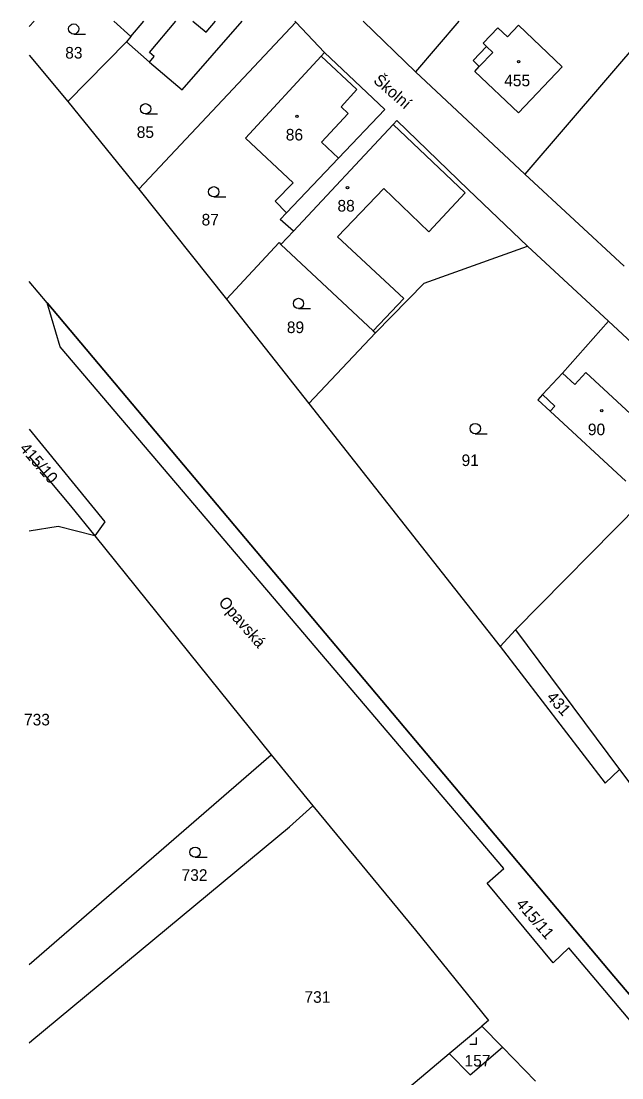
# Model space of a CAD drawing. Extents: x -504601 to -503665, y -1079870 to -1078626.
# Drawn here: x -504600.9 to -504513, y -1078780.8 to -1078626.2 of the extents above; entities that cross this region are included whole.
import ezdxf

# ---------------------------------------------------------------- set-up
doc = ezdxf.new("R2010")
doc.units = 0
for name, color, linetype in [('Hranice parcel', 7, 'Continuous'), ('Parcelní čísla', 7, 'Continuous'), ('Pop  PČ popisy', 7, 'Continuous'), ('Vnitřní kresba', 7, 'Continuous'), ('Vrstva 54', 7, 'Continuous'), ('Značky budov', 7, 'Continuous'), ('Značky kultur', 7, 'Continuous')]:
    doc.layers.add(name, color=color, linetype=linetype)

msp = doc.modelspace()

# ---------------------------------------------------------------- linework, layer by layer
at = {"layer": 'Hranice parcel'}
for p, q in [((-504599.72, -1078626.96), (-504598.99, -1078626.15)), ((-504587.33, -1078626.15), (-504584.87, -1078628.4)), ((-504583.69, -1078650.73), (-504560.74, -1078626.29)), ((-504560.74, -1078626.29), (-504560.89, -1078626.15)), ((-504556.52, -1078630.76), (-504560.74, -1078626.29)), ((-504550.86, -1078626.15), (-504543.22, -1078633.58)), ((-504536.89, -1078626.15), (-504543.22, -1078633.58)), ((-504508.05, -1078626.15), (-504527.23, -1078648.54)), ((-504594.06, -1078637.92), (-504585.52, -1078629.17)), ((-504584.87, -1078628.4), (-504585.52, -1078629.17)), ((-504599.72, -1078631.15), (-504594.06, -1078637.92)), ((-504543.22, -1078633.58), (-504527.23, -1078648.54)), ((-504594.06, -1078637.92), (-504583.69, -1078650.73)), ((-504527.23, -1078648.54), (-504512.71, -1078662.02)), ((-504583.69, -1078650.73), (-504570.88, -1078666.85)), ((-504563.74, -1078652.52), (-504562.08, -1078654.23)), ((-504561.09, -1078656.9), (-504562.9, -1078658.83)), ((-504515.01, -1078670.07), (-504526.83, -1078659.1)), ((-504595.19, -1078673.8), (-504597.09, -1078667.4)), ((-504570.88, -1078666.85), (-504558.84, -1078682.13)), ((-504515.01, -1078670.07), (-504521.74, -1078677.69)), ((-504497.46, -1078686.36), (-504515.01, -1078670.07)), ((-504558.84, -1078682.13), (-504549.08, -1078671.78)), ((-504558.84, -1078682.13), (-504530.83, -1078717.69)), ((-504528.6, -1078715.23), (-504510.4, -1078696.81)), ((-504590.14, -1078701.47), (-504564.35, -1078733.55)), ((-504530.83, -1078717.69), (-504528.6, -1078715.23)), ((-504528.6, -1078715.23), (-504513.37, -1078735.66)), ((-504564.35, -1078733.55), (-504558.23, -1078741)), ((-504513.37, -1078735.66), (-504512.16, -1078737.29)), ((-504538.29, -1078777.24), (-504533.54, -1078773.23)), ((-504533.54, -1078773.23), (-504530.49, -1078776.34)), ((-504525.66, -1078781.28), (-504530.49, -1078776.34)), ((-504599.72, -1078829.02), (-504538.29, -1078777.24))]:
    msp.add_line(p, q, dxfattribs=at)
for points in [[(-504585.52, -1078629.17), (-504582.12, -1078632.17), (-504577.37, -1078636.19), (-504568.57, -1078626.15)], [(-504584.87, -1078628.4), (-504582.98, -1078626.15)], [(-504533.89, -1078632.8), (-504534.81, -1078631.93), (-504532.83, -1078629.85), (-504533.33, -1078629.38), (-504531.17, -1078627.13), (-504529.78, -1078628.45), (-504528.15, -1078626.72), (-504521.75, -1078632.83), (-504528.16, -1078639.59), (-504534.56, -1078633.51), (-504533.89, -1078632.8)], [(-504556.52, -1078630.76), (-504557, -1078631.27), (-504568.1, -1078643.27)], [(-504562.08, -1078654.23), (-504554.47, -1078646.21), (-504547.69, -1078639.08), (-504556.52, -1078630.76)], [(-504526.83, -1078659.1), (-504535.5, -1078650.8), (-504545.97, -1078640.71), (-504546.48, -1078641.26), (-504561.09, -1078656.9)], [(-504568.1, -1078643.27), (-504561.12, -1078649.82), (-504563.74, -1078652.52)], [(-504561.09, -1078656.9), (-504563, -1078655.2), (-504562.08, -1078654.23)], [(-504570.88, -1078666.85), (-504563.18, -1078658.57), (-504562.9, -1078658.83)], [(-504562.9, -1078658.83), (-504549.41, -1078671.47), (-504549.08, -1078671.78)], [(-504549.08, -1078671.78), (-504541.95, -1078664.49), (-504526.83, -1078659.1)], [(-504597.09, -1078667.4), (-504599.72, -1078664.27)], [(-504597.09, -1078667.4), (-504514.19, -1078765.94), (-504428.7, -1078866.55), (-504382.03, -1078924.33)], [(-504382.03, -1078926.66), (-504397.6, -1078907.92), (-504520.79, -1078761.79), (-504523.08, -1078763.96), (-504532.75, -1078752.34), (-504530.29, -1078750.16), (-504595.19, -1078673.8)], [(-504521.74, -1078677.69), (-504524.65, -1078680.82), (-504525.34, -1078681.56), (-504523.53, -1078683.23), (-504512.44, -1078693.49)], [(-504599.72, -1078685.86), (-504588.66, -1078699.42), (-504590.14, -1078701.47)], [(-504599.72, -1078689.85), (-504593.67, -1078697.08), (-504590.14, -1078701.47)], [(-504590.14, -1078701.47), (-504595.47, -1078700.11), (-504599.72, -1078700.82)], [(-504530.83, -1078717.69), (-504515.48, -1078737.7), (-504513.37, -1078735.66)], [(-504599.72, -1078764.2), (-504564.35, -1078733.55)], [(-504599.72, -1078775.67), (-504599.34, -1078775.34), (-504561.66, -1078744.08), (-504558.23, -1078741)], [(-504558.23, -1078741), (-504543.24, -1078759.21), (-504532.57, -1078772.41), (-504533.54, -1078773.23)], [(-504538.29, -1078777.24), (-504535.24, -1078780.35), (-504530.49, -1078776.34)]]:
    msp.add_lwpolyline(points, dxfattribs=at)
at = {"layer": 'Vnitřní kresba'}
for p, q in [((-504582.14, -1078630.76), (-504578.29, -1078626.15)), ((-504575.81, -1078626.15), (-504573.86, -1078627.78)), ((-504573.86, -1078627.78), (-504572.5, -1078626.15)), ((-504581.43, -1078631.35), (-504582.14, -1078630.76)), ((-504533.89, -1078632.8), (-504531.92, -1078630.72)), ((-504531.92, -1078630.72), (-504532.83, -1078629.85)), ((-504582.12, -1078632.17), (-504581.43, -1078631.35)), ((-504557, -1078631.27), (-504551.82, -1078636.18)), ((-504551.82, -1078636.18), (-504554.11, -1078638.67)), ((-504554.11, -1078638.67), (-504553.08, -1078639.67)), ((-504553.08, -1078639.67), (-504556.98, -1078643.85)), ((-504546.48, -1078641.26), (-504535.94, -1078651.28)), ((-504556.98, -1078643.85), (-504554.47, -1078646.21)), ((-504547.86, -1078650.67), (-504554.62, -1078657.74)), ((-504541.27, -1078656.98), (-504547.86, -1078650.67)), ((-504535.94, -1078651.28), (-504541.27, -1078656.98)), ((-504554.62, -1078657.74), (-504544.93, -1078666.76)), ((-504544.93, -1078666.76), (-504549.41, -1078671.47))]:
    msp.add_line(p, q, dxfattribs=at)
for points in [[(-504507.17, -1078687.86), (-504518.29, -1078677.57), (-504519.94, -1078679.35), (-504521.74, -1078677.69)], [(-504524.65, -1078680.82), (-504522.86, -1078682.51), (-504523.53, -1078683.23)]]:
    msp.add_lwpolyline(points, dxfattribs=at)
at = {"layer": 'Vrstva 54'}
for points in [[(-504428.7, -1078866.55), (-504514.19, -1078765.94), (-504597.09, -1078667.4)], [(-504558.84, -1078682.13), (-504530.83, -1078717.69), (-504515.48, -1078737.7), (-504513.37, -1078735.66), (-504512.16, -1078737.29), (-504507.63, -1078743.89), (-504506.21, -1078745.96), (-504510.04, -1078749.73), (-504485.94, -1078776.97), (-504483.44, -1078779.79), (-504481.39, -1078782.11), (-504435.49, -1078833.98), (-504407.21, -1078868.45)]]:
    msp.add_lwpolyline(points, dxfattribs=at)
at = {"layer": 'Značky budov'}
for centre in [(-504528.15, -1078632.08), (-504560.56, -1078640.09), (-504553.17, -1078650.53), (-504515.99, -1078683.15)]:
    msp.add_circle(centre, 0.175, dxfattribs=at)
at = {"layer": 'Značky kultur'}
for p, q in [((-504593.22, -1078628.05), (-504591.47, -1078628.05)), ((-504582.7, -1078639.73), (-504580.95, -1078639.73)), ((-504572.74, -1078651.87), (-504570.99, -1078651.87)), ((-504560.34, -1078668.22), (-504558.59, -1078668.22)), ((-504534.48, -1078686.54), (-504532.73, -1078686.54)), ((-504575.47, -1078748.53), (-504573.72, -1078748.53)), ((-504535.3, -1078775.9), (-504534.3, -1078775.9)), ((-504534.3, -1078775.9), (-504534.3, -1078774.9))]:
    msp.add_line(p, q, dxfattribs=at)
for centre in [(-504593.22, -1078627.3), (-504582.7, -1078638.98), (-504572.74, -1078651.12), (-504560.34, -1078667.47), (-504534.48, -1078685.79), (-504575.47, -1078747.78)]:
    msp.add_circle(centre, 0.75, dxfattribs=at)

# ---------------------------------------------------------------- texts
at = {"layer": 'Parcelní čísla'}
for s, p in [('83', (-504594.46, -1078631.63)), ('455', (-504530.25, -1078635.68)), ('85', (-504584, -1078643.24)), ('86', (-504562.2, -1078643.62)), ('88', (-504554.64, -1078654.02)), ('87', (-504574.51, -1078656.06)), ('89', (-504562.04, -1078671.81)), ('90', (-504518.01, -1078686.76)), ('91', (-504536.48, -1078691.27)), ('733', (-504600.49, -1078729.23)), ('732', (-504577.44, -1078751.98)), ('731', (-504559.47, -1078769.83)), ('157', (-504536.05, -1078779.15))]:
    msp.add_text(s, height=1.7, dxfattribs=at).set_placement(p)
for s, rotation, p in [('415/10', 311, (-504601.23, -1078688.75)), ('431', 312, (-504524.16, -1078725.19)), ('415/11', 311, (-504528.63, -1078755.45))]:
    msp.add_text(s, height=1.7, rotation=rotation, dxfattribs=at).set_placement(p)
at = {"layer": 'Pop  PČ popisy'}
for s, rotation, p in [('Školní', 319, (-504549.51, -1078635.02)), ('Opavská', 311, (-504572.14, -1078711.27))]:
    msp.add_text(s, height=1.7, rotation=rotation, dxfattribs=at).set_placement(p)

doc.saveas('drawing.dxf')
